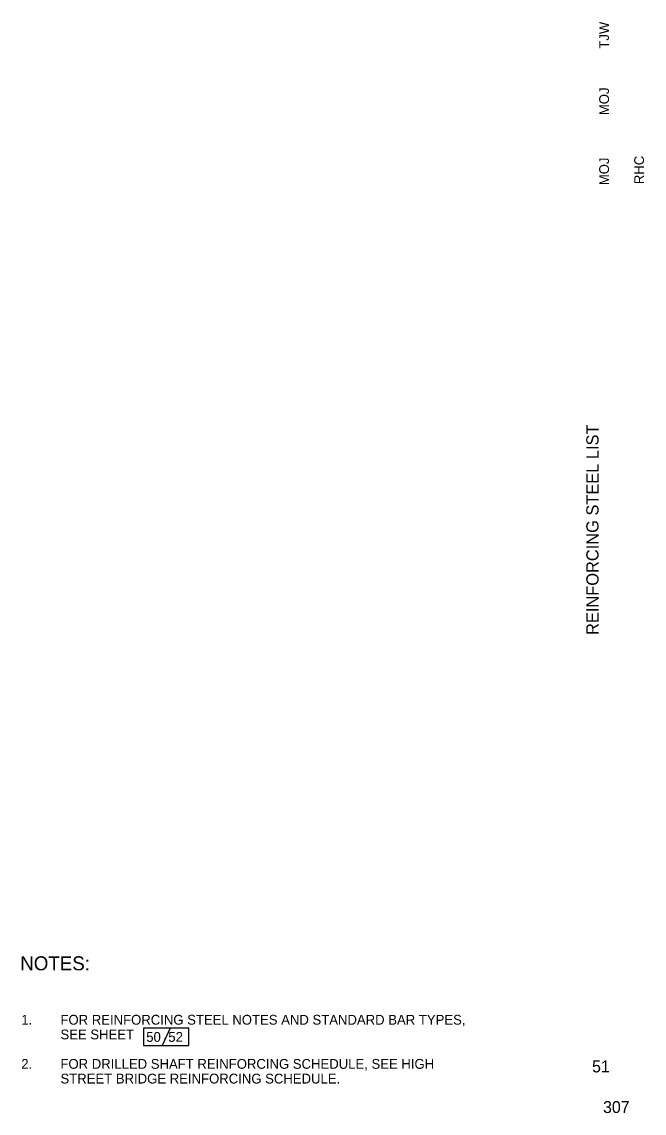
# Model space of a CAD drawing. Extents: x 24.5 to 33.4, y 1.1 to 16.7.
import ezdxf

# ---------------------------------------------------------------- set-up
doc = ezdxf.new("R2010")
doc.units = 0
for name, color, linetype in [('BR_P_Gen_Text', 7, 'Continuous'), ('BR_X_Slab_Const_Joint', 7, 'Continuous'), ('BR_X_Slab_Object', 7, 'Continuous')]:
    doc.layers.add(name, color=color, linetype=linetype)

msp = doc.modelspace()

# ---------------------------------------------------------------- linework, layer by layer
at = {"layer": 'BR_X_Slab_Const_Joint'}
msp.add_line((26.636, 2.298), (26.521, 2.048), dxfattribs=at)
msp.add_line((26.636, 2.298), (26.521, 2.048), dxfattribs=at)
msp.add_lwpolyline([(26.254, 2.048), (26.904, 2.048), (26.904, 2.298), (26.254, 2.298)], close=True, dxfattribs=at)
msp.add_lwpolyline([(26.254, 2.048), (26.904, 2.048), (26.904, 2.298), (26.254, 2.298)], close=True, dxfattribs=at)

# ---------------------------------------------------------------- texts
at = {"layer": 'BR_P_Gen_Text'}
for s, height, p in [('50', 0.14, (26.295, 2.101)), ('52', 0.14, (26.61, 2.101)), ('51', 0.17, (32.661, 1.665)), ('307', 0.17, (32.818, 1.085))]:
    msp.add_text(s, height=height, dxfattribs=at).set_placement(p)
at = {"layer": 'BR_X_Slab_Const_Joint'}
for s, height, p in [('NOTES:', 0.2, (24.496, 3.122)), ('NOTES:', 0.2, (24.496, 3.122)), ('1.', 0.14, (24.51, 2.346)), ('1.', 0.14, (24.51, 2.346)), ('FOR REINFORCING STEEL NOTES AND STANDARD BAR TYPES, ', 0.14, (25.07, 2.346)), ('FOR REINFORCING STEEL NOTES AND STANDARD BAR TYPES, ', 0.14, (25.07, 2.346)), ('SEE SHEET        .', 0.14, (25.07, 2.136)), ('SEE SHEET        .', 0.14, (25.07, 2.136)), ('2.', 0.14, (24.51, 1.716)), ('FOR DRILLED SHAFT REINFORCING SCHEDULE, SEE HIGH ', 0.14, (25.07, 1.716)), ('STREET BRIDGE REINFORCING SCHEDULE.', 0.14, (25.07, 1.506))]:
    msp.add_text(s, height=height, dxfattribs=at).set_placement(p)
at = {"layer": 'BR_X_Slab_Object'}
for s, height, p in [('TJW', 0.14, (32.903, 16.278)), ('MOJ', 0.14, (32.903, 15.329)), ('MOJ', 0.14, (32.903, 14.329)), ('RHC', 0.14, (33.403, 14.344)), ('REINFORCING STEEL LIST', 0.175, (32.754, 7.91))]:
    msp.add_text(s, height=height, rotation=90, dxfattribs=at).set_placement(p)

doc.saveas('drawing.dxf')
